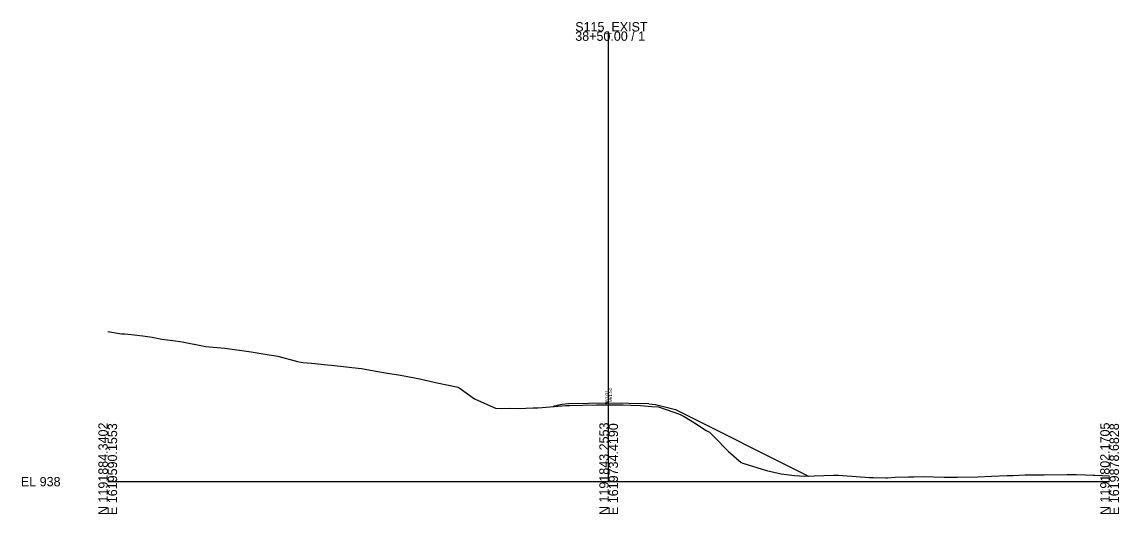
# Model space of a CAD drawing. Extents: x 1620351 to 1620680, y 1192592 to 1195749.
# Drawn here: x 1620351.1 to 1620679.6, y 1195091.8 to 1195239.1 of the extents above; entities that cross this region are included whole.
import ezdxf

# ---------------------------------------------------------------- set-up
doc = ezdxf.new("R2010")
doc.units = 0
for name, color, linetype in [('RD_GPK_XS_Cell', 7, 'Continuous'), ('RD_XS_EarthShd', 7, 'Continuous'), ('RD_XS_ExGround', 7, 'Continuous'), ('RD_XS_Pave', 7, 'Continuous'), ('RD_XS_TieSlope', 7, 'Continuous'), ('RD_XS_TX_Elev_EX', 7, 'Continuous'), ('RD_XS_TX_Elev_PR', 7, 'Continuous')]:
    doc.layers.add(name, color=color, linetype=linetype)

msp = doc.modelspace()

# ---------------------------------------------------------------- linework, layer by layer
at = {"layer": 'RD_GPK_XS_Cell'}
for p, q in [((1620526.76, 1195101.47), (1620526.76, 1195236.22)), ((1620376.76, 1195101.47), (1620526.76, 1195101.47)), ((1620526.76, 1195101.47), (1620676.76, 1195101.47))]:
    msp.add_line(p, q, dxfattribs=at)
at = {"layer": 'RD_XS_EarthShd'}
for p, q in [((1620514.76, 1195124.74), (1620512.76, 1195124.58)), ((1620538.76, 1195124.74), (1620540.76, 1195124.58))]:
    msp.add_line(p, q, dxfattribs=at)
at = {"layer": 'RD_XS_ExGround'}
msp.add_lwpolyline([(1620376.76, 1195146.38), (1620380.9, 1195145.7), (1620381.85, 1195145.68), (1620384.7, 1195145.43), (1620387.26, 1195145.15), (1620390.03, 1195144.68), (1620392.96, 1195144.16), (1620397.08, 1195143.59), (1620398.35, 1195143.41), (1620399.03, 1195143.32), (1620405.64, 1195142.03), (1620406, 1195141.97), (1620411.81, 1195141.42), (1620414.01, 1195141.08), (1620419, 1195140.39), (1620419.74, 1195140.28), (1620424.47, 1195139.56), (1620427.7, 1195139.05), (1620433.62, 1195137.43), (1620435.18, 1195137.1), (1620437.74, 1195136.92), (1620442.6, 1195136.48), (1620443.77, 1195136.36), (1620447.37, 1195135.97), (1620449.81, 1195135.65), (1620452.74, 1195135.35), (1620458.72, 1195134.27), (1620459.31, 1195134.15), (1620459.97, 1195134.04), (1620464.38, 1195133.34), (1620466.51, 1195132.96), (1620470.18, 1195132.22), (1620471.94, 1195131.86), (1620474.08, 1195131.37), (1620474.88, 1195131.17), (1620481.74, 1195129.76), (1620482.34, 1195129.32), (1620486.59, 1195126.3), (1620487.65, 1195125.77), (1620492.86, 1195123.46), (1620494.79, 1195123.41), (1620497.09, 1195123.44), (1620499.73, 1195123.34), (1620504.13, 1195123.54), (1620505.54, 1195123.55), (1620506.83, 1195123.65), (1620509.2, 1195123.84), (1620513.95, 1195124.24), (1620514.69, 1195124.3), (1620515, 1195124.31), (1620523.16, 1195124.49), (1620524.17, 1195124.48), (1620526.25, 1195124.48), (1620526.76, 1195124.48), (1620531.14, 1195124.45), (1620533.41, 1195124.35), (1620536.3, 1195124.25), (1620539.65, 1195124), (1620541.67, 1195123.84), (1620545.93, 1195122.37), (1620547.94, 1195121.68), (1620549.34, 1195121.02), (1620552.42, 1195119.07), (1620555.96, 1195116.82), (1620556.97, 1195116.28), (1620558.27, 1195115.01), (1620562.68, 1195110.46), (1620566.48, 1195107.25), (1620566.93, 1195107), (1620574.02, 1195104.76), (1620578.46, 1195103.84), (1620582.45, 1195103.3), (1620585.42, 1195103.09), (1620594.04, 1195103.4), (1620595.54, 1195103.39), (1620596.92, 1195103.29), (1620604.87, 1195102.73), (1620605.96, 1195102.73), (1620609.79, 1195102.61), (1620610.27, 1195102.66), (1620612.53, 1195102.83), (1620616.54, 1195102.89), (1620618.18, 1195102.91), (1620620.94, 1195103.05), (1620627.26, 1195102.79), (1620629.7, 1195102.84), (1620631.26, 1195102.86), (1620637.31, 1195102.94), (1620641.43, 1195103.09), (1620646.1, 1195103.3), (1620647.9, 1195103.3), (1620651.46, 1195103.48), (1620656.1, 1195103.51), (1620657.13, 1195103.53), (1620664.09, 1195103.6), (1620665.23, 1195103.6), (1620666.76, 1195103.6), (1620669.58, 1195103.48), (1620671.87, 1195103.37), (1620672.3, 1195103.37), (1620676.76, 1195103.18)], dxfattribs=at)
at = {"layer": 'RD_XS_Pave'}
for p, q in [((1620526.76, 1195124.98), (1620514.76, 1195124.74)), ((1620538.76, 1195124.74), (1620526.76, 1195124.98))]:
    msp.add_line(p, q, dxfattribs=at)
at = {"layer": 'RD_XS_TieSlope'}
for p, q in [((1620512.76, 1195124.58), (1620510.11, 1195123.92)), ((1620540.76, 1195124.58), (1620546.76, 1195123.08)), ((1620546.76, 1195123.08), (1620586.65, 1195103.14))]:
    msp.add_line(p, q, dxfattribs=at)

# ---------------------------------------------------------------- texts
at = {"layer": 'RD_GPK_XS_Cell'}
for s, p in [('S115_EXIST', (1620516.76, 1195236.22)), ('38+50.00 / 1', (1620516.76, 1195233.42)), ('EL 938', (1620350.76, 1195100.07))]:
    msp.add_text(s, height=2.8, dxfattribs=at).set_placement(p)
for s, p in [('N 1191884.3402', (1620376.76, 1195091.47)), ('E 1619590.1553', (1620379.56, 1195091.47)), ('N 1191843.2553', (1620526.76, 1195091.47)), ('E 1619734.4190', (1620529.56, 1195091.47)), ('N 1191802.1705', (1620676.76, 1195091.47)), ('E 1619878.6828', (1620679.56, 1195091.47))]:
    msp.add_text(s, height=2.8, rotation=90, dxfattribs=at).set_placement(p)
at = {"layer": 'RD_XS_TX_Elev_EX'}
msp.add_text('961.01', height=1, rotation=90, dxfattribs=at).set_placement((1620526.66, 1195124.58))
at = {"layer": 'RD_XS_TX_Elev_PR'}
msp.add_text(' 961.52', height=1, rotation=90, dxfattribs=at).set_placement((1620527.76, 1195124.98))

doc.saveas('drawing.dxf')
